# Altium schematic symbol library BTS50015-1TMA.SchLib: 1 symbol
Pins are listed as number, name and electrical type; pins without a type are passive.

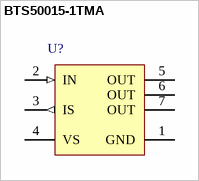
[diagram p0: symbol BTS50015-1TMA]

## BTS50015-1TMA
designator U?
Smart High-Side Power Switch, 1 Channel, 39 A Load Current, -40 to 150 degC, PG-TO-220-7-232, Reel, Green; Manufacturer: Infineon; PartNumber: BTS50015-1TMA; Channels: 1; Green: TRUE; Group: Automotive Qualified; Load Current (typ): 39 A; Ptot (max): 200 W; Recommended Operating Voltage Max.: 28 V; Recommended Operating Voltage Min.: 5.5 V; RON @ 25degreesC: 1.5 mOhm; RON(max) @ 150degreesC: 3 mOhm; toff (max): 700 us
footprint INF-PG-TO-220-7-232 (FM, 7-Leads, Body 10x4.4mm, Pitch 1.27mm)
pins: 1 GND (power) "GrouND; Ground connection", 2 IN (in) "INput; Input signal for channel activation. HIGH active", 3 IS (out) "Sense; Provides signal for diagnosis", 4 VS (power) "Supply Voltage; Battery voltage", 5 OUT (power) "OUTput; Protected high side power output", 6 OUT (power) "OUTput; Protected high side power output", 7 OUT (power) "OUTput; Protected high side power output"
